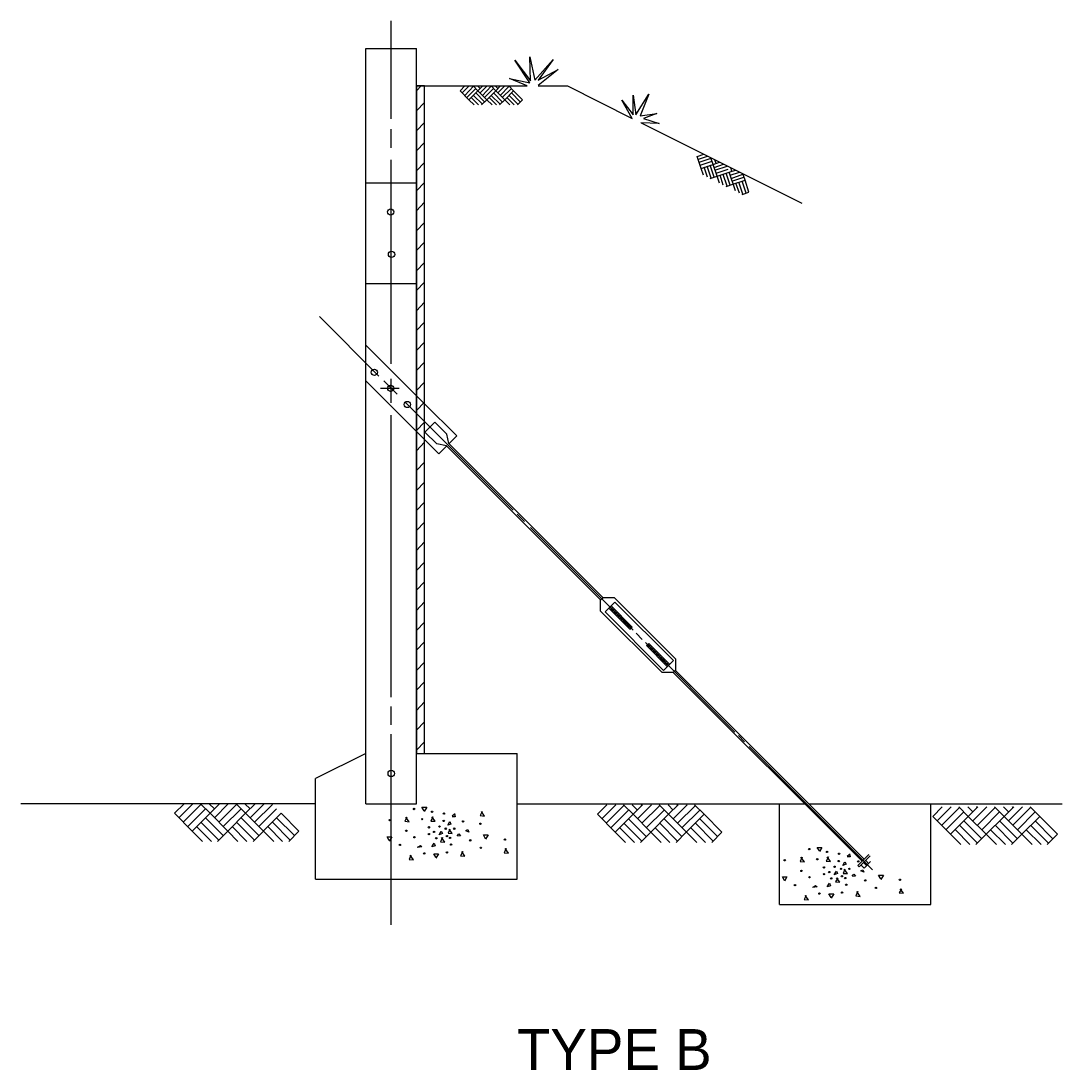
# Model space of a CAD drawing. Extents: x -0.04 to 2.79, y -0.02 to 1.81.
# Drawn here: x 1.7598 to 2.0247, y 1.3881 to 1.6551 of the extents above; entities that cross this region are included whole.
import ezdxf

# ---------------------------------------------------------------- set-up
doc = ezdxf.new("R2010")
doc.units = 0
doc.layers.add('Level 1', color=7, linetype='Continuous')
doc.layers.add('Level 2', color=7, linetype='Continuous')

msp = doc.modelspace()

# ---------------------------------------------------------------- linework, layer by layer
at = {"layer": 'Level 1'}
for p, q in [((1.85395, 1.63023), (1.85395, 1.65511)), ((1.84753, 1.45587), (1.84753, 1.64814)), ((1.84753, 1.64814), (1.86038, 1.64814)), ((1.86038, 1.45587), (1.86038, 1.64814)), ((1.86038, 1.63857), (1.8886, 1.63857)), ((1.86249, 1.46872), (1.86249, 1.63857)), ((1.87152, 1.63734), (1.87275, 1.63857)), ((1.87377, 1.63508), (1.87152, 1.63734)), ((1.87206, 1.63679), (1.87384, 1.63857)), ((1.87268, 1.63618), (1.87493, 1.6385)), ((1.87323, 1.63563), (1.87548, 1.63789)), ((1.87377, 1.63508), (1.87603, 1.63734)), ((1.87603, 1.63734), (1.8748, 1.63857)), ((1.87774, 1.63454), (1.87548, 1.63679)), ((1.87664, 1.63789), (1.87596, 1.63857)), ((1.87603, 1.63734), (1.87726, 1.63857)), ((1.87603, 1.63734), (1.87726, 1.63857)), ((1.87828, 1.63508), (1.87603, 1.63734)), ((1.87664, 1.63679), (1.87842, 1.63857)), ((1.87719, 1.6385), (1.87712, 1.63857)), ((1.87719, 1.63618), (1.87945, 1.6385)), ((1.87774, 1.63563), (1.87999, 1.63789)), ((1.87828, 1.63508), (1.88061, 1.63734)), ((1.88061, 1.63734), (1.87938, 1.63857)), ((1.88225, 1.63454), (1.87999, 1.63679)), ((1.88115, 1.63789), (1.88047, 1.63857)), ((1.88061, 1.63734), (1.88177, 1.63857)), ((1.88061, 1.63734), (1.88177, 1.63857)), ((1.88416, 1.63378), (1.88061, 1.63734)), ((1.88115, 1.63679), (1.88293, 1.63857)), ((1.8817, 1.6385), (1.88163, 1.63857)), ((1.8817, 1.63618), (1.88396, 1.6385)), ((1.88225, 1.63563), (1.88457, 1.63789)), ((1.88286, 1.63508), (1.88512, 1.63734)), ((1.88512, 1.63734), (1.88389, 1.63857)), ((1.88683, 1.63454), (1.88457, 1.63679)), ((1.88737, 1.63508), (1.88512, 1.63734)), ((1.89134, 1.63857), (1.89886, 1.63857)), ((1.89886, 1.63857), (1.91533, 1.6303)), ((1.87507, 1.63378), (1.87377, 1.63508)), ((1.87623, 1.63378), (1.87432, 1.63563)), ((1.87719, 1.63392), (1.87493, 1.63618)), ((1.87698, 1.63378), (1.87828, 1.63508)), ((1.87965, 1.63378), (1.87828, 1.63508)), ((1.88074, 1.63378), (1.8789, 1.63563)), ((1.8817, 1.63392), (1.87945, 1.63618)), ((1.88156, 1.63378), (1.88286, 1.63508)), ((1.88526, 1.63378), (1.88341, 1.63563)), ((1.88621, 1.63392), (1.88396, 1.63618)), ((1.88608, 1.63378), (1.88737, 1.63508)), ((1.91759, 1.6292), (1.95846, 1.60877)), ((1.85395, 1.62285), (1.85395, 1.62756)), ((1.93187, 1.62066), (1.93351, 1.62121)), ((1.9329, 1.61759), (1.93187, 1.62066)), ((1.93214, 1.61991), (1.93447, 1.62073)), ((1.85395, 1.56789), (1.85395, 1.61977)), ((1.93235, 1.61916), (1.93542, 1.62018)), ((1.93262, 1.61841), (1.93563, 1.61943)), ((1.9329, 1.61759), (1.9359, 1.61861)), ((1.93447, 1.6154), (1.93365, 1.61793)), ((1.93542, 1.61512), (1.9344, 1.61813)), ((1.93618, 1.61533), (1.93515, 1.61841)), ((1.9359, 1.61861), (1.93536, 1.62025)), ((1.9359, 1.61861), (1.93754, 1.61916)), ((1.9359, 1.61861), (1.93754, 1.61916)), ((1.93693, 1.6156), (1.9359, 1.61861)), ((1.93618, 1.61786), (1.93857, 1.61868)), ((1.93665, 1.61888), (1.93638, 1.61977)), ((1.93638, 1.61711), (1.93946, 1.61813)), ((1.93741, 1.61916), (1.93741, 1.61923)), ((1.93344, 1.61588), (1.9329, 1.61759)), ((1.93515, 1.61499), (1.93693, 1.6156)), ((1.93665, 1.61635), (1.93973, 1.61738)), ((1.93693, 1.6156), (1.94, 1.61663)), ((1.93754, 1.61383), (1.93693, 1.6156)), ((1.9385, 1.61335), (1.93768, 1.61588)), ((1.93946, 1.61307), (1.93843, 1.61608)), ((1.94021, 1.61335), (1.93918, 1.61635)), ((1.94, 1.61663), (1.94158, 1.61718)), ((1.94, 1.61663), (1.94158, 1.61718)), ((1.94158, 1.61184), (1.94, 1.61663)), ((1.94021, 1.61588), (1.9426, 1.61663)), ((1.94069, 1.6169), (1.94041, 1.61772)), ((1.94048, 1.61506), (1.94349, 1.61615)), ((1.94069, 1.61437), (1.94376, 1.61533)), ((1.94151, 1.61711), (1.94144, 1.61724)), ((1.94404, 1.61458), (1.94349, 1.61622)), ((1.84753, 1.61396), (1.86038, 1.61396)), ((1.93925, 1.61301), (1.94096, 1.61355)), ((1.94096, 1.61355), (1.94404, 1.61458)), ((1.9426, 1.6113), (1.94171, 1.61383)), ((1.94349, 1.61102), (1.94246, 1.6141)), ((1.94431, 1.6113), (1.94328, 1.6143)), ((1.94499, 1.61157), (1.94404, 1.61458)), ((1.94328, 1.61096), (1.94499, 1.61157)), ((1.84753, 1.58833), (1.86038, 1.58833)), ((1.8357, 1.57992), (1.85087, 1.56475)), ((1.84753, 1.57261), (1.86256, 1.55757)), ((1.84753, 1.56352), (1.86243, 1.54862)), ((1.8521, 1.56352), (1.85552, 1.5601)), ((1.85395, 1.55792), (1.85395, 1.564)), ((1.85128, 1.56167), (1.856, 1.56167)), ((1.85744, 1.55819), (1.88498, 1.53064)), ((1.86243, 1.55771), (1.8707, 1.54951)), ((1.85395, 1.483), (1.85395, 1.55477)), ((1.86256, 1.55046), (1.86509, 1.55299)), ((1.86509, 1.55299), (1.86817, 1.54999)), ((1.86256, 1.55046), (1.86557, 1.54746)), ((1.86865, 1.54759), (1.86817, 1.54999)), ((1.86865, 1.54746), (1.8707, 1.54951)), ((1.86256, 1.54848), (1.86612, 1.54493)), ((1.86803, 1.54698), (1.86557, 1.54746)), ((1.86612, 1.54493), (1.86817, 1.54698)), ((1.86803, 1.54698), (1.90726, 1.50775)), ((1.86865, 1.54759), (1.90788, 1.50829)), ((1.88601, 1.52955), (1.88792, 1.5277)), ((1.88942, 1.5262), (1.91553, 1.50009)), ((1.90726, 1.50775), (1.90788, 1.50836)), ((1.90726, 1.50494), (1.90726, 1.50775)), ((1.90781, 1.50836), (1.91075, 1.50836)), ((1.90843, 1.50474), (1.91089, 1.5072)), ((1.90979, 1.50556), (1.91007, 1.50583)), ((1.90993, 1.50624), (1.91533, 1.50084)), ((1.91075, 1.50836), (1.92633, 1.49278)), ((1.91089, 1.5072), (1.92579, 1.49237)), ((1.90726, 1.50494), (1.92292, 1.48929)), ((1.90843, 1.50474), (1.92326, 1.48984)), ((1.90938, 1.50569), (1.91471, 1.5003)), ((1.90986, 1.50522), (1.91041, 1.50576)), ((1.91013, 1.50522), (1.91041, 1.50542)), ((1.9102, 1.50481), (1.91075, 1.50542)), ((1.91054, 1.50481), (1.91082, 1.50508)), ((1.91061, 1.50446), (1.91116, 1.50501)), ((1.91089, 1.5044), (1.91116, 1.50467)), ((1.91095, 1.50405), (1.9115, 1.50467)), ((1.9113, 1.50405), (1.91157, 1.50433)), ((1.91137, 1.50371), (1.91191, 1.50426)), ((1.91171, 1.5033), (1.91225, 1.50392)), ((1.91171, 1.50364), (1.91191, 1.50392)), ((1.91205, 1.5033), (1.91232, 1.50358)), ((1.91212, 1.50296), (1.91266, 1.50351)), ((1.91246, 1.50255), (1.91307, 1.50317)), ((1.91246, 1.50289), (1.91273, 1.50317)), ((1.9128, 1.50255), (1.91307, 1.50282)), ((1.91287, 1.50221), (1.91342, 1.50276)), ((1.91321, 1.50214), (1.91348, 1.50241)), ((1.91321, 1.5018), (1.91383, 1.50235)), ((1.91355, 1.5018), (1.91383, 1.50207)), ((1.91362, 1.50146), (1.91417, 1.502)), ((1.91396, 1.50139), (1.91424, 1.50166)), ((1.91396, 1.50105), (1.91458, 1.50159)), ((1.9143, 1.50105), (1.91458, 1.50132)), ((1.91437, 1.50071), (1.91492, 1.50125)), ((1.91471, 1.50064), (1.91499, 1.50091)), ((1.91471, 1.5003), (1.91533, 1.50084)), ((1.91635, 1.49927), (1.91786, 1.4977)), ((1.91868, 1.49695), (1.94144, 1.47412)), ((1.91895, 1.49613), (1.9195, 1.49667)), ((1.91895, 1.49613), (1.92422, 1.49079)), ((1.91929, 1.49606), (1.91957, 1.49633)), ((1.91929, 1.49572), (1.91991, 1.49626)), ((1.9195, 1.49667), (1.92483, 1.49141)), ((1.9197, 1.49537), (1.92025, 1.49592)), ((1.9197, 1.49572), (1.91991, 1.49592)), ((1.92005, 1.49531), (1.92032, 1.49558)), ((1.92005, 1.49496), (1.92066, 1.49551)), ((1.92046, 1.49462), (1.921, 1.49517)), ((1.92046, 1.49496), (1.92066, 1.49517)), ((1.9208, 1.49455), (1.92107, 1.49483)), ((1.9208, 1.49421), (1.92141, 1.49476)), ((1.92121, 1.49387), (1.92175, 1.49442)), ((1.92121, 1.49421), (1.92141, 1.49442)), ((1.92155, 1.4938), (1.92182, 1.49408)), ((1.92155, 1.49346), (1.92216, 1.49401)), ((1.92196, 1.49305), (1.92251, 1.49367)), ((1.92196, 1.49346), (1.92216, 1.49367)), ((1.9223, 1.49305), (1.92257, 1.49332)), ((1.92237, 1.49271), (1.92292, 1.49326)), ((1.92271, 1.4923), (1.92326, 1.49291)), ((1.92271, 1.49264), (1.92292, 1.49291)), ((1.92305, 1.4923), (1.92333, 1.49257)), ((1.92312, 1.49196), (1.92367, 1.4925)), ((1.92633, 1.49278), (1.92633, 1.48984)), ((1.92326, 1.48984), (1.92579, 1.49237)), ((1.92346, 1.49155), (1.92401, 1.49216)), ((1.92346, 1.49189), (1.92367, 1.49216)), ((1.9238, 1.49155), (1.92408, 1.49175)), ((1.92387, 1.4912), (1.92442, 1.49175)), ((1.92422, 1.49114), (1.92442, 1.49141)), ((1.92572, 1.48929), (1.92633, 1.48991)), ((1.92633, 1.48984), (1.97438, 1.44179)), ((1.92572, 1.48929), (1.92285, 1.48929)), ((1.92572, 1.48929), (1.97384, 1.44124)), ((1.85395, 1.47596), (1.85395, 1.48068)), ((1.85395, 1.42504), (1.85395, 1.47357)), ((1.94233, 1.47323), (1.9439, 1.47166)), ((1.84753, 1.46872), (1.83474, 1.46229)), ((1.86038, 1.46872), (1.88601, 1.46872)), ((1.88601, 1.43666), (1.88601, 1.46872)), ((1.94506, 1.47049), (1.9765, 1.43905)), ((1.83474, 1.43666), (1.83474, 1.46229)), ((1.83474, 1.45587), (1.75976, 1.45587)), ((1.79879, 1.45347), (1.80125, 1.45587)), ((1.79995, 1.45231), (1.80351, 1.45587)), ((1.80105, 1.45122), (1.80556, 1.45573)), ((1.80788, 1.45347), (1.80542, 1.45587)), ((1.80898, 1.45457), (1.80768, 1.45587)), ((1.80788, 1.45347), (1.81027, 1.45587)), ((1.80788, 1.45347), (1.81027, 1.45587)), ((1.80898, 1.45231), (1.81253, 1.45587)), ((1.81014, 1.45573), (1.80993, 1.45587)), ((1.81014, 1.45122), (1.81465, 1.45573)), ((1.8169, 1.45347), (1.81451, 1.45587)), ((1.81807, 1.45457), (1.81677, 1.45587)), ((1.8169, 1.45347), (1.81936, 1.45587)), ((1.8169, 1.45347), (1.81936, 1.45587)), ((1.81807, 1.45231), (1.82162, 1.45587)), ((1.81916, 1.45573), (1.81902, 1.45587)), ((1.81916, 1.45122), (1.82374, 1.45573)), ((1.84753, 1.45587), (1.86038, 1.45587)), ((1.88601, 1.45587), (1.95928, 1.45587)), ((1.90644, 1.4532), (1.90884, 1.45559)), ((1.90761, 1.45204), (1.91116, 1.45559)), ((1.9087, 1.45095), (1.91321, 1.45546)), ((1.91553, 1.4532), (1.91307, 1.45559)), ((1.91663, 1.4543), (1.91533, 1.45559)), ((1.91553, 1.4532), (1.91793, 1.45559)), ((1.91553, 1.4532), (1.91793, 1.45559)), ((1.91663, 1.45204), (1.92018, 1.45559)), ((1.91779, 1.45546), (1.91759, 1.45559)), ((1.91779, 1.45095), (1.9223, 1.45546)), ((1.92456, 1.4532), (1.92216, 1.45559)), ((1.92572, 1.4543), (1.92442, 1.45559)), ((1.92456, 1.4532), (1.92702, 1.45559)), ((1.92456, 1.4532), (1.92702, 1.45559)), ((1.92572, 1.45204), (1.92927, 1.45559)), ((1.92681, 1.45546), (1.92668, 1.45559)), ((1.92681, 1.45095), (1.93139, 1.45546)), ((1.93365, 1.4532), (1.93119, 1.45559)), ((1.95279, 1.43024), (1.95279, 1.45594)), ((1.96024, 1.45587), (2.02469, 1.45587)), ((1.99127, 1.43024), (1.99127, 1.45594)), ((1.99181, 1.45265), (1.99421, 1.45512)), ((1.99291, 1.45156), (1.99646, 1.45512)), ((2.00084, 1.45265), (1.99844, 1.45512)), ((2.002, 1.45382), (2.0007, 1.45512)), ((2.00084, 1.45265), (2.0033, 1.45512)), ((2.00084, 1.45265), (2.0033, 1.45512)), ((2.002, 1.45156), (2.00555, 1.45512)), ((2.00316, 1.45491), (2.00296, 1.45512)), ((2.00993, 1.45265), (2.00747, 1.45512)), ((2.01109, 1.45382), (2.00979, 1.45512)), ((2.00993, 1.45265), (2.01239, 1.45512)), ((2.00993, 1.45265), (2.01239, 1.45512)), ((2.01109, 1.45156), (2.01464, 1.45512)), ((2.01218, 1.45491), (2.01205, 1.45512)), ((2.01902, 1.45265), (2.01656, 1.45512)), ((1.8033, 1.4489), (1.79879, 1.45347)), ((1.80221, 1.45006), (1.80672, 1.45457)), ((1.8033, 1.4489), (1.80788, 1.45347)), ((1.81239, 1.4489), (1.80788, 1.45347)), ((1.81123, 1.45006), (1.81581, 1.45457)), ((1.81239, 1.4489), (1.8169, 1.45347)), ((1.82408, 1.4463), (1.8169, 1.45347)), ((1.82032, 1.45006), (1.82483, 1.45457)), ((1.82142, 1.4489), (1.82599, 1.45347)), ((1.83051, 1.4489), (1.82599, 1.45347)), ((1.91095, 1.44869), (1.90644, 1.4532)), ((1.90986, 1.44978), (1.91437, 1.4543)), ((1.91095, 1.44869), (1.91553, 1.4532)), ((1.92005, 1.44869), (1.91553, 1.4532)), ((1.91888, 1.44978), (1.92346, 1.4543)), ((1.92005, 1.44869), (1.92456, 1.4532)), ((1.93173, 1.44602), (1.92456, 1.4532)), ((1.92797, 1.44978), (1.93249, 1.4543)), ((1.92907, 1.44869), (1.93365, 1.4532)), ((1.93816, 1.44869), (1.93365, 1.4532)), ((1.99633, 1.44814), (1.99181, 1.45265)), ((1.99407, 1.4504), (1.99858, 1.45491)), ((1.99523, 1.44931), (1.99974, 1.45382)), ((1.99633, 1.44814), (2.00084, 1.45265)), ((2.00542, 1.44814), (2.00084, 1.45265)), ((2.00316, 1.4504), (2.00767, 1.45491)), ((2.00425, 1.44924), (2.00877, 1.45382)), ((2.00542, 1.44814), (2.00993, 1.45265)), ((2.0171, 1.44555), (2.00993, 1.45265)), ((2.01218, 1.4504), (2.01669, 1.45491)), ((2.01334, 1.44924), (2.01786, 1.45382)), ((2.01444, 1.44814), (2.01902, 1.45265)), ((2.02353, 1.44814), (2.01902, 1.45265)), ((1.80822, 1.4463), (1.80446, 1.45006)), ((1.81014, 1.44664), (1.80556, 1.45122)), ((1.81123, 1.4478), (1.80672, 1.45231)), ((1.81725, 1.4463), (1.81349, 1.45006)), ((1.81916, 1.44664), (1.81465, 1.45122)), ((1.82032, 1.4478), (1.81581, 1.45231)), ((1.82634, 1.4463), (1.82258, 1.45006)), ((1.82825, 1.44664), (1.82374, 1.45122)), ((1.82934, 1.4478), (1.82483, 1.45231)), ((1.91588, 1.44602), (1.91212, 1.44978)), ((1.91779, 1.44637), (1.91321, 1.45095)), ((1.91888, 1.44753), (1.91437, 1.45204)), ((1.9249, 1.44602), (1.92114, 1.44978)), ((1.92681, 1.44637), (1.9223, 1.45095)), ((1.92797, 1.44753), (1.92346, 1.45204)), ((1.93399, 1.44602), (1.93023, 1.44978)), ((1.9359, 1.44637), (1.93139, 1.45095)), ((1.937, 1.44753), (1.93249, 1.45204)), ((2.00316, 1.44589), (1.99858, 1.4504)), ((2.00425, 1.44698), (1.99974, 1.45156)), ((2.01218, 1.44589), (2.00767, 1.4504)), ((2.01334, 1.44698), (2.00877, 1.45156)), ((2.02127, 1.44589), (2.01669, 1.4504)), ((2.02237, 1.44698), (2.01786, 1.45156)), ((1.80597, 1.4463), (1.8033, 1.4489)), ((1.8098, 1.4463), (1.81239, 1.4489)), ((1.81499, 1.4463), (1.81239, 1.4489)), ((1.81882, 1.4463), (1.82148, 1.4489)), ((1.82791, 1.4463), (1.83051, 1.4489)), ((1.91362, 1.44602), (1.91095, 1.44869)), ((1.91745, 1.44602), (1.92005, 1.44869)), ((1.92264, 1.44602), (1.92005, 1.44869)), ((1.92647, 1.44602), (1.92907, 1.44869)), ((1.93556, 1.44602), (1.93816, 1.44869)), ((1.99892, 1.44555), (1.99633, 1.44814)), ((2.00125, 1.44555), (1.99749, 1.44931)), ((2.00275, 1.44555), (2.00542, 1.44814)), ((2.00801, 1.44555), (2.00542, 1.44814)), ((2.01027, 1.44555), (2.00651, 1.44924)), ((2.01184, 1.44555), (2.01444, 1.44814)), ((2.01936, 1.44555), (2.0156, 1.44924)), ((2.02093, 1.44555), (2.02353, 1.44814)), ((1.97274, 1.44015), (1.97555, 1.44295)), ((1.97309, 1.4398), (1.97589, 1.44261)), ((1.97274, 1.44015), (1.97309, 1.4398)), ((1.97356, 1.44028), (1.97432, 1.43953)), ((1.97418, 1.4409), (1.97493, 1.44015)), ((1.97432, 1.43953), (1.97596, 1.44117)), ((1.97473, 1.44145), (1.97548, 1.44069)), ((1.83474, 1.43666), (1.88601, 1.43666)), ((1.95279, 1.43024), (1.99127, 1.43024))]:
    msp.add_line(p, q, dxfattribs=at)
for points in [[(1.88854, 1.63857), (1.88409, 1.64048), (1.88922, 1.63939), (1.88546, 1.64513), (1.88942, 1.63987)], [(1.88942, 1.63987), (1.88922, 1.64602), (1.89052, 1.64007), (1.89517, 1.64534), (1.89141, 1.64007), (1.89646, 1.64274), (1.89141, 1.63871)], [(1.86038, 1.63734), (1.86161, 1.63857)], [(1.86038, 1.63221), (1.86249, 1.63433)], [(1.91533, 1.6303), (1.91266, 1.63495), (1.91553, 1.63119), (1.91553, 1.63625), (1.91622, 1.63119), (1.9195, 1.63652), (1.91731, 1.63098), (1.92155, 1.6316), (1.9182, 1.6303), (1.92216, 1.629), (1.91752, 1.6292)], [(1.86038, 1.62715), (1.86249, 1.62927)], [(1.86038, 1.62203), (1.86249, 1.62422)], [(1.86038, 1.61697), (1.86249, 1.61909)], [(1.86038, 1.61191), (1.86249, 1.61403)], [(1.86038, 1.60679), (1.86249, 1.60897)], [(1.86038, 1.60173), (1.86249, 1.60385)], [(1.86038, 1.59667), (1.86249, 1.59879)], [(1.86038, 1.59154), (1.86249, 1.59366)], [(1.86038, 1.58649), (1.86249, 1.5886)], [(1.86038, 1.58136), (1.86249, 1.58355)], [(1.86038, 1.5763), (1.86249, 1.57842)], [(1.86038, 1.57124), (1.86249, 1.57336)], [(1.86038, 1.56612), (1.86249, 1.5683)], [(1.86038, 1.56106), (1.86249, 1.56318)], [(1.86038, 1.556), (1.86249, 1.55812)], [(1.86038, 1.55087), (1.86249, 1.55299)], [(1.86038, 1.54575), (1.86249, 1.54794)], [(1.86038, 1.54069), (1.86249, 1.54281)], [(1.86038, 1.53563), (1.86249, 1.53775)], [(1.86038, 1.53051), (1.86249, 1.53263)], [(1.86038, 1.52545), (1.86249, 1.52757)], [(1.86038, 1.52032), (1.86249, 1.52251)], [(1.86038, 1.51526), (1.86249, 1.51738)], [(1.86038, 1.51021), (1.86249, 1.51233)], [(1.86038, 1.50508), (1.86249, 1.50727)], [(1.86038, 1.50002), (1.86249, 1.50214)], [(1.86038, 1.49496), (1.86249, 1.49708)], [(1.86038, 1.48984), (1.86249, 1.49196)], [(1.86038, 1.48478), (1.86249, 1.4869)], [(1.86038, 1.47965), (1.86249, 1.48184)], [(1.86038, 1.4746), (1.86249, 1.47671)], [(1.86038, 1.46954), (1.86249, 1.47166)]]:
    msp.add_lwpolyline(points, dxfattribs=at)
msp.add_lwpolyline([(1.86249, 1.46872), (1.86249, 1.63857), (1.86038, 1.63857), (1.86038, 1.46872)], close=True, dxfattribs=at)
msp.add_lwpolyline([(1.86249, 1.46872), (1.86249, 1.63857), (1.86038, 1.63857), (1.86038, 1.46872)], close=True, dxfattribs=at)
for centre in [(1.85386, 1.6065), (1.85406, 1.5957), (1.8497, 1.56571), (1.85384, 1.56164), (1.85809, 1.5575), (1.85398, 1.4636)]:
    msp.add_circle(centre, 0.000801, dxfattribs=at)
at = {"layer": 'Level 2'}
for points in [[(1.85798, 1.45245), (1.85744, 1.45142), (1.85853, 1.45129), (1.85771, 1.45245)], [(1.86236, 1.45409), (1.86181, 1.45505), (1.86304, 1.45505), (1.86236, 1.45395)], [(1.86461, 1.45259), (1.86407, 1.45149), (1.86516, 1.45142), (1.86434, 1.45259)], [(1.87008, 1.45341), (1.87022, 1.45259), (1.86947, 1.45259)], [(1.86947, 1.45279), (1.87008, 1.45334)], [(1.87712, 1.45395), (1.87664, 1.45286), (1.87774, 1.45272), (1.87692, 1.45395)], [(1.86837, 1.4504), (1.86892, 1.45136), (1.86919, 1.45067), (1.86837, 1.4504)], [(1.85347, 1.44657), (1.85293, 1.44746), (1.85416, 1.44746), (1.85347, 1.44637)], [(1.86619, 1.44801), (1.86673, 1.4489), (1.86701, 1.44828), (1.86619, 1.44801)], [(1.86707, 1.44732), (1.86653, 1.44623), (1.86762, 1.44609), (1.8668, 1.44732)], [(1.86892, 1.44944), (1.86844, 1.44842), (1.86953, 1.44828), (1.86871, 1.44944)], [(1.87076, 1.44773), (1.87117, 1.44821), (1.87158, 1.44773), (1.8709, 1.44767)], [(1.87295, 1.4491), (1.8735, 1.44931), (1.8737, 1.44869), (1.87295, 1.44896)], [(1.87801, 1.44698), (1.87746, 1.44794), (1.87869, 1.44794), (1.87801, 1.44684)], [(1.86085, 1.44493), (1.8614, 1.44527), (1.86181, 1.44493), (1.86058, 1.44479)], [(1.86434, 1.44493), (1.86489, 1.44589), (1.86516, 1.4452), (1.86434, 1.44493)], [(1.88327, 1.44452), (1.88273, 1.44343), (1.88382, 1.44329), (1.883, 1.44452)], [(1.96297, 1.44391), (1.96242, 1.44479), (1.96359, 1.44479), (1.96297, 1.4437)], [(1.85901, 1.44281), (1.85853, 1.44172), (1.85962, 1.44158), (1.8588, 1.44281)], [(1.86536, 1.44227), (1.86482, 1.44315), (1.86605, 1.44315), (1.86536, 1.44206)], [(1.8722, 1.4437), (1.87165, 1.44261), (1.87275, 1.44254), (1.87193, 1.4437)], [(1.95853, 1.44227), (1.95805, 1.44117), (1.95914, 1.4411), (1.95825, 1.44227)], [(1.96523, 1.4424), (1.96468, 1.44131), (1.96577, 1.44117), (1.96495, 1.4424)], [(1.97063, 1.44315), (1.97076, 1.4424), (1.97001, 1.4424)], [(1.97001, 1.44254), (1.97063, 1.44309)], [(1.96892, 1.44021), (1.96946, 1.4411), (1.96974, 1.44049), (1.96892, 1.44021)], [(1.96946, 1.43926), (1.96898, 1.43816), (1.97008, 1.4381), (1.96926, 1.43926)], [(1.9735, 1.43885), (1.97404, 1.43905), (1.97425, 1.43851), (1.9735, 1.43878)], [(1.95408, 1.43632), (1.95354, 1.43728), (1.9547, 1.43728), (1.95408, 1.43618)], [(1.96673, 1.43782), (1.96728, 1.43871), (1.96755, 1.4381), (1.96673, 1.43782)], [(1.96762, 1.43707), (1.96707, 1.43605), (1.96816, 1.43591), (1.96734, 1.43707)], [(1.97131, 1.43748), (1.97172, 1.43796), (1.97213, 1.43748), (1.97145, 1.43741)], [(1.97855, 1.4368), (1.97801, 1.43769), (1.97924, 1.43769), (1.97855, 1.43659)], [(1.96147, 1.43475), (1.96194, 1.43509), (1.96242, 1.43475), (1.96119, 1.43454)], [(1.96495, 1.43475), (1.9655, 1.43564), (1.96577, 1.43502), (1.96495, 1.43475)], [(1.98382, 1.43427), (1.98327, 1.43324), (1.98436, 1.43311), (1.98354, 1.43427)], [(1.95962, 1.43256), (1.95907, 1.43153), (1.96017, 1.4314), (1.95935, 1.43256)], [(1.96591, 1.43201), (1.96536, 1.43297), (1.96659, 1.43297), (1.96591, 1.43188)], [(1.97274, 1.43352), (1.9722, 1.43242), (1.97329, 1.43229), (1.97247, 1.43352)]]:
    msp.add_lwpolyline(points, dxfattribs=at)
for centre in [(1.85981, 1.45456), (1.86437, 1.45384), (1.86741, 1.45339), (1.85358, 1.45171), (1.86186, 1.45197), (1.86357, 1.44989), (1.86627, 1.45008), (1.86733, 1.45152), (1.87227, 1.45141), (1.87668, 1.4508), (1.85783, 1.44901), (1.85989, 1.44738), (1.86357, 1.44818), (1.8649, 1.44872), (1.86544, 1.44712), (1.86787, 1.44955), (1.86814, 1.44765), (1.86896, 1.4472), (1.87003, 1.44955), (1.8562, 1.44541), (1.86923, 1.44549), (1.87409, 1.44658), (1.87679, 1.44469), (1.8829, 1.44677), (1.96035, 1.44435), (1.86239, 1.44324), (1.86816, 1.44351), (1.96241, 1.44176), (1.96491, 1.44363), (1.96796, 1.44318), (1.95413, 1.4415), (1.96411, 1.43968), (1.96681, 1.43987), (1.96788, 1.44131), (1.96841, 1.43933), (1.97058, 1.43933), (1.97282, 1.4412), (1.95837, 1.4388), (1.96043, 1.43717), (1.96411, 1.43797), (1.96545, 1.43851), (1.96598, 1.4369), (1.96868, 1.43744), (1.96951, 1.43698), (1.97463, 1.43637), (1.98344, 1.43656), (1.95674, 1.43519), (1.96977, 1.43527), (1.97733, 1.43447), (1.96294, 1.43303), (1.96871, 1.4333)]:
    msp.add_circle(centre, 0.000174, dxfattribs=at)

# ---------------------------------------------------------------- texts
msp.add_text('TYPE B', height=0.010417).set_placement((1.88598, 1.38813))

doc.saveas('drawing.dxf')
